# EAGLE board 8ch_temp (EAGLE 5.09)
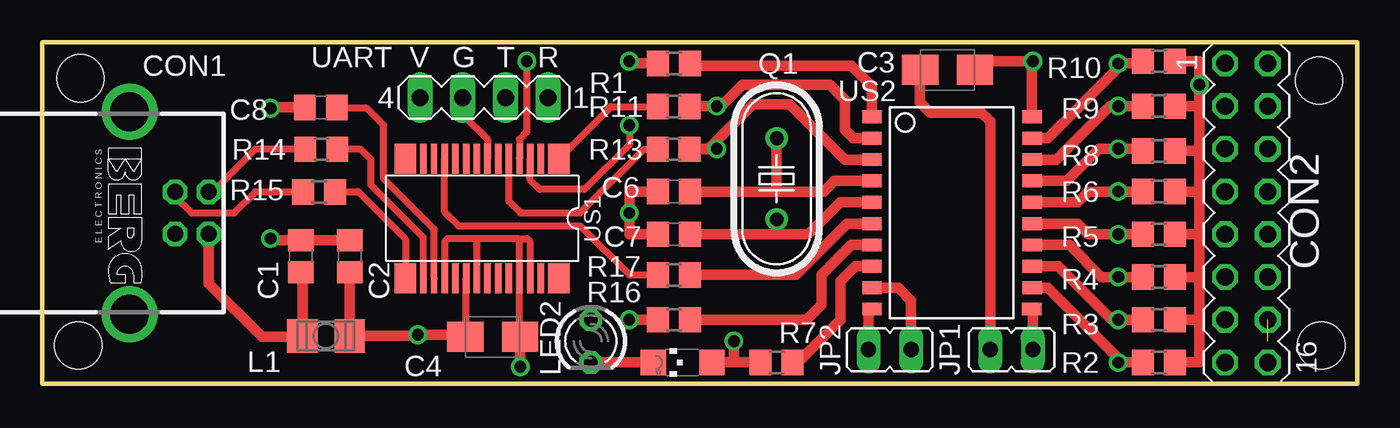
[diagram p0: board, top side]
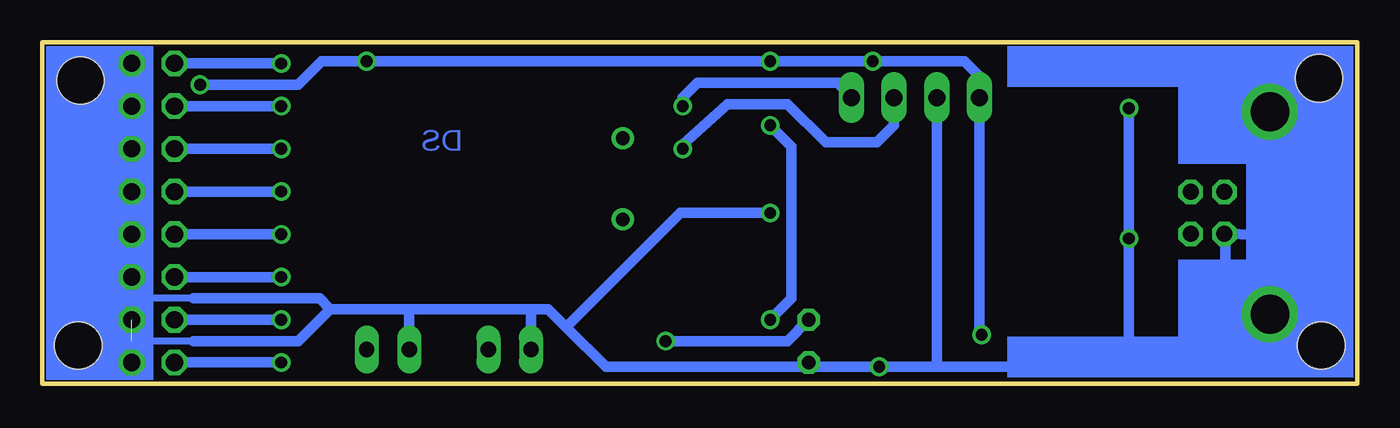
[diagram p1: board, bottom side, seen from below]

Size 78.23 x 20.32 mm. Coordinates in mm from the lower left corner, seen from the top.
Outline: 0,0 0,20.32 78.23,20.32 78.23,0 0,0
Copper layers (1*16): Top 0.035mm / dielectric 1.5mm / Bottom 0.035mm
Design rules "default": minimum track width 10mil, minimum drill 24mil, track to track 8mil, track to pad 8mil, pad to pad 8mil, via to via 8mil, smd to smd 8mil, copper to edge 40mil, drill to drill 8mil, minimum pad ring 10mil, minimum via ring 8mil, stop-mask expansion 4mil, vias tented up to drill 0mil, thermal gap 10mil
Holes 2.8 mm at 2.29,18.16 75.95,18.03 76.07,2.29 2.16,2.29

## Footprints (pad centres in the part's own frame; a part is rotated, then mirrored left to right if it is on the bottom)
C0805 = smd 1.3 x 1.5: 1 -0.95,0; 2 0.95,0
B/3528-21W = smd 2.15 x 1.8: + 1.625,0; - -1.625,0
PN61729-S = drill 0.95 octagon: 1 1.25,4.71; 2 -1.25,4.71; 3 -1.25,2.71; 4 1.25,2.71 | drill 2.3 pad 2.9 round: S1 -6.02,0; S2 6.02,0
MA08-2 = drill 1.016 octagon: 1 -8.89,-1.27; 2 -8.89,1.27; 3 -6.35,-1.27; 4 -6.35,1.27; 5 -3.81,-1.27; 6 -3.81,1.27; 7 -1.27,-1.27; 8 -1.27,1.27; 9 1.27,-1.27; 10 1.27,1.27; 11 3.81,-1.27; 12 3.81,1.27; 13 6.35,-1.27; 14 6.35,1.27; 15 8.89,-1.27; 16 8.89,1.27
JP1 = drill 0.914 long: 1 0,-1.27; 2 0,1.27
L3225P = smd 1.8 x 2: 1 -1.4,0; 2 1.4,0
LED3MM = drill 0.813 octagon: A -1.27,0; K 1.27,0
CHIPLED_1206 = smd 1.5 x 1.5: A 0,-1.75; C 0,1.75
HC49U70 = drill 0.813 round: 1 -2.413,0; 2 2.413,0
R0805 = smd 1.3 x 1.5: 1 -0.95,0; 2 0.95,0
MA04-1 = drill 1.016 long: 1 -3.81,0; 2 -1.27,0; 3 1.27,0; 4 3.81,0
TSSOP28 = smd 1.27 x 1.778: 1 -4.547,-3.556; 14 4.572,-3.556; 15 4.572,3.556; 28 -4.547,3.556 | smd 0.381 x 1.778: 2 -3.48,-3.556; 3 -2.845,-3.556; 4 -2.21,-3.556; 5 -1.575,-3.556; 6 -0.94,-3.556; 7 -0.305,-3.556; 8 0.33,-3.556; 9 0.965,-3.556; 10 1.6,-3.556; 11 2.235,-3.556; 12 2.87,-3.556; 13 3.505,-3.556; 16 3.505,3.556; 17 2.87,3.556; 18 2.235,3.556; 19 1.6,3.556; 20 0.965,3.556; 21 0.33,3.556; 22 -0.305,3.556; 23 -0.94,3.556; 24 -1.575,3.556; 25 -2.21,3.556; 26 -2.845,3.556; 27 -3.48,3.556
SO20L = smd 0.762 x 1.143: 1 -5.08,-5.131; 2 -3.81,-5.131; 3 -2.54,-5.131; 4 -1.27,-5.131; 5 0,-5.131; 6 1.27,-5.131; 7 2.54,-5.131; 8 3.81,-5.131; 9 5.08,-5.131; 10 6.35,-5.131; 11 6.35,4.369; 12 5.08,4.394; 13 3.81,4.394; 14 2.54,4.394; 15 1.27,4.394; 16 0,4.394; 17 -1.27,4.394; 18 -2.54,4.394; 19 -3.81,4.394; 20 -5.08,4.394

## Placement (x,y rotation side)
C1  100nF  [C0805]  15.39,7.59 90 top
C2  100nF  [C0805]  18.31,7.59 90 top
C3  [B/3528-21W]  53.85,18.67 0 top
C4  [B/3528-21W]  26.8,2.79 180 top
C6  100nF  [C0805]  37.59,11.43 0 top
C7  100nF  [C0805]  37.59,8.89 0 top
C8  10nF  [C0805]  16.59,16.43 180 top
CON1  USB  [PN61729-S]  5.21,10.16 270 top
CON2  [MA08-2]  71.63,10.16 270 top
JP1  [JP1]  57.66,2.03 270 top
JP2  [JP1]  50.42,2.03 270 top
L1  10uH  [L3225P]  16.89,2.84 0 top
LED1  [LED3MM]  32.64,2.54 270 top
LED2  [CHIPLED_1206]  38.1,1.27 90 top
Q1  [HC49U70]  43.69,12.19 90 top
R1  1k  [R0805]  37.59,19.05 0 top
R2  1k  [R0805]  66.42,1.27 180 top
R3  1k  [R0805]  66.42,3.81 180 top
R4  1k  [R0805]  66.42,6.35 180 top
R5  1k  [R0805]  66.42,8.89 180 top
R6  1k  [R0805]  66.42,11.43 180 top
R7  1k  [R0805]  43.69,1.27 0 top
R8  1k  [R0805]  66.42,13.84 180 top
R9  1k  [R0805]  66.42,16.51 180 top
R10  1k  [R0805]  66.42,19.18 180 top
R11  47R  [R0805]  37.57,16.48 0 top
R13  47R  [R0805]  37.57,13.94 0 top
R14  47R  [R0805]  16.61,13.94 0 top
R15  47R  [R0805]  16.48,11.4 0 top
R16  47R  [R0805]  37.59,3.81 0 top
R17  47R  [R0805]  37.59,6.48 0 top
UART  [MA04-1]  26.29,17.02 180 top
US1  [TSSOP28]  26.19,9.83 180 top
US2  AT90S2313S  [SO20L]  54.48,10.79 270 top

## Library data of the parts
C1-C4 C6-C8 L1 R1-R11 R13-R17 = rcl
CON1 = con-berg
CON2 UART = con-lstb
JP1 JP2 = jumper
LED1 LED2 = led
Q1 = crystal
US1 = DS
US2 = avr-4

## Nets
+5V: C2.1 C3.+ C4.+ L1.2 R1.1 R2.1 R3.1 R4.1 R5.1 R6.1 R8.1 R9.1 R10.1 UART.4 US1.4 US1.20 US2.20
CF1: JP1.2 US2.11
CF2: JP2.2 US2.9
CL6: C7.2 Q1.1 US2.5
CTS: R17.2 US2.6
GND: C1.2 C2.2 C3.- C4.- C6.1 C7.1 C8.2 CON1.4 CON1.S1 CON1.S2 CON2.2 CON2.4 CON2.6 CON2.8 CON2.10 CON2.12 CON2.14 CON2.16 JP1.1 JP2.1 LED1.K LED2.C UART.3 US1.7 US1.18 US1.21 US1.25 US1.26 US2.10
IO1: CON2.1 R10.2 US2.19
IO2: CON2.3 R9.2 US2.18
IO3: CON2.5 R8.2 US2.17
IO4: CON2.7 R6.2 US2.16
IO5: CON2.9 R5.2 US2.15
IO6: CON2.11 R4.2 US2.14
IO7: CON2.13 R3.2 US2.13
IO8: CON2.15 R2.2 US2.12
N$1: R14.2 US1.16
N$2: R15.2 US1.15
N$3: CON1.2 R14.1
N$4: CON1.3 R15.1
N$6: C8.1 US1.17
N$7: R16.1 US1.3
N$10: R11.1 US1.1
N$11: R13.1 US1.5
N$18: R17.1 US1.11
N$29: C6.2 Q1.2 US2.4
N$31: R1.2 US2.1
N$32: LED1.A LED2.A R7.1
P_ON: R7.2 US2.8
RTS: R16.2 US2.7
RXD: R11.2 UART.1 US2.2
TXD: R13.2 UART.2 US2.3
USB+: C1.1 CON1.1 L1.1

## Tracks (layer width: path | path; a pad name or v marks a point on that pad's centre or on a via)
+5V  (via drill 0.7)
  Top 0.406: 58.88,19.13 58.88,19.36 | US1.4 28.4,14.55 28.83,14.99 v28.83,19.18 | US1.20 25.22,2.84 C4.+
  Top 0.61: R10.1 68.83,19.18 v68.83,17.78 68.83,16.51 | 68.83,3.81 68.83,1.27 R2.1 | 68.83,8.89 68.83,6.35 | 68.83,13.84 68.83,11.43 | 68.83,16.51 R9.1 | 68.83,13.84 R8.1 | 68.83,16.51 68.83,13.84 | 68.83,11.43 R6.1 | 68.83,8.89 R5.1 | 68.83,11.43 68.83,8.89 | 68.83,6.35 R4.1 | 68.83,3.81 R3.1 | 68.83,6.35 68.83,3.81 | US2.20 58.88,19.13 v58.93,19.18 55.88,19.18 C3.+ | R1.1 34.8,19.05 v34.92,19.18 | C4.+ 24.64,2.79 24.51,2.92 v22.35,2.92 22.28,2.85 L1.2 18.29,6.11 C2.1
  Bottom 0.61: v68.83,17.78 62.99,17.78 61.59,19.18 v58.93,19.18 v34.92,19.18 v28.83,19.18 23.37,19.18 22.48,18.29 UART.4 22.48,3.18 22.35,3.05 v22.35,2.92
CF1
  Top 0.61: US2.11 58.93,4.45 JP1.2
CF2
  Top 0.61: US2.9 50.93,5.71 51.69,4.95 JP2.2
CL6
  Top 0.61: C7.2 43.69,8.89 | 43.69,8.89 45.59,8.89 47.5,10.79 US2.5 | 43.69,8.89 Q1.1
CTS
  Top 0.61: US2.6 47.88,9.52 44.83,6.48 R17.2
GND  (via drill 0.7)  (1 unrouted)
  Top 0.406: US1.7 26.49,14.53 25.02,16 UART.3 | US1.26 29.03,8.43 28.83,8.64 28.32,8.64 | US1.18 23.95,8.46 24.13,8.64 25.91,8.64 | 28.32,8.64 25.91,8.64 | 28.32,8.64 28.4,8.56 US1.25 28.4,2.56 C4.- | US1.21 25.86,8.59 25.91,8.64
  Top 0.61: US2.10 49.15,4.45 JP2.1 | C3.- 52.22,16.74 52.83,16.13 55.88,16.13 56.39,15.62 JP1.1 | LED1.K LED2.C | C6.1 34.92,11.43 v34.92,10.16 34.92,8.89 C7.1 | C4.- 28.42,1.04 v28.45,1.02 | C2.2 C1.2 13.68,8.54 v13.59,8.64 | C8.2 13.64,16.43 v13.59,16.38
  Bottom 0.406: 69.22,2.54 72.9,2.54 | 69.22,5.08 72.9,5.08
  Bottom 0.61: CON2.2 CON2.4 CON2.6 CON2.8 CON2.10 CON2.12 72.9,5.08 CON2.14 72.9,2.54 CON2.16 | 61.09,4.45 62.99,2.54 69.22,2.54 | 49.15,4.45 56.39,4.45 | 56.39,4.45 61.09,4.45 | 47.05,3.37 44.7,1.02 32.64,1.02 | 47.05,3.37 48.13,4.45 49.15,4.45 | 24.89,1.02 v28.45,1.02 32.64,1.02 | 56.39,4.45 JP1.1 | 49.15,4.45 JP2.1 | 32.64,1.02 LED1.K | v34.92,10.16 40.26,10.16 47.05,3.37 | UART.3 25.02,1.14 24.89,1.02 | 13.59,1.02 24.89,1.02 | 13.59,1.02 v13.59,8.64 v13.59,16.38 | 13.59,1.02 10.41,1.02 7.87,3.56 7.87,3.81 | 7.87,3.81 7.87,8.87 CON1.4 5.08,8.83 CON1.S1 | CON1.S2 7.54,4.14 7.87,3.81 | 61.09,4.45 61.72,5.08 69.22,5.08
IO1  (via drill 0.7)
  Top 0.61: R10.2 65.47,19.05 v64.01,19.05 64.01,18.8 59.82,14.61 US2.19
  Bottom 0.61: v64.01,19.05 CON2.1
IO2  (via drill 0.7)
  Top 0.61: R9.2 v64.01,16.51 63.5,16.51 60.33,13.34 US2.18
  Bottom 0.61: v64.01,16.51 CON2.3
IO3  (via drill 0.7)
  Top 0.61: R8.2 65.47,13.97 v64.01,13.97 62.87,13.97 60.96,12.07 US2.17
  Bottom 0.61: v64.01,13.97 CON2.5
IO4  (via drill 0.7)
  Top 0.61: R6.2 v64.01,11.43 62.23,11.43 61.59,10.79 US2.16
  Bottom 0.61: v64.01,11.43 CON2.7
IO5  (via drill 0.7)
  Top 0.61: R5.2 v64.01,8.89 62.23,8.89 61.59,9.52 US2.15
  Bottom 0.61: v64.01,8.89 CON2.9
IO6  (via drill 0.7)
  Top 0.61: R4.2 v64.01,6.35 62.99,6.35 61.09,8.25 US2.14
  Bottom 0.61: v64.01,6.35 CON2.11
IO7  (via drill 0.7)
  Top 0.61: R3.2 v64.01,3.81 63.63,3.81 60.45,6.98 US2.13
  Bottom 0.61: v64.01,3.81 CON2.13
IO8  (via drill 0.7)
  Top 0.61: R2.2 v64.01,1.27 64.01,1.52 59.82,5.71 US2.12
  Bottom 0.61: v64.01,1.27 CON2.15
N$1
  Top 0.406: R14.2 18.95,13.95 19.56,13.34 19.56,11.81 22.68,8.69 US1.16
N$2
  Top 0.406: US1.15 21.61,8.61 18.8,11.43 17.46,11.43 R15.2
N$3
  Top 0.406: CON1.2 10.14,11.41 12.7,13.97 15.64,13.97 R14.1
N$4
  Top 0.406: CON1.3 7.92,11.13 8.89,10.16 11.43,10.16 12.7,11.43 15.51,11.43 R15.1
N$6
  Top 0.406: US1.17 23.32,9.2 20.32,12.19 20.32,15.37 19.3,16.38 17.71,16.38 C8.1
N$7  (via drill 0.7)
  Top 0.406: v34.92,15.37 34.92,14.22 32.26,11.56 29.59,11.56 29.03,12.12 US1.3
  Top 0.61: v34.92,3.81 R16.1
  Bottom 0.61: v34.92,3.81 33.66,5.08 33.66,14.1 v34.92,15.37
N$10
  Top 0.406: R11.1 33.83,16.48 US1.1
N$11
  Top 0.406: R13.1 35.79,13.95 32,10.16 28.45,10.16 27.76,10.85 US1.5
N$18
  Top 0.406: R17.1 34.92,6.48 32,9.4 24.77,9.4 23.95,10.21 US1.11
N$29
  Top 0.61: C6.2 43.81,11.43 | 43.81,11.43 46.48,11.43 47.12,12.07 US2.4 | Q1.2 43.69,11.56 43.81,11.43
N$31
  Top 0.61: US2.1 49.35,17.7 48.13,18.92 38.67,18.92 R1.2
N$32  (via drill 0.7)
  Top 0.61: 41.15,1.27 R7.1 | 41.15,1.27 LED2.A | v41.15,2.54 41.15,1.27
  Bottom 0.61: v41.15,2.54 33.91,2.54 LED1.A
P_ON
  Top 0.61: US2.8 48.39,6.98 47.5,6.1 47.5,3.81 44.96,1.27 R7.2
RTS
  Top 0.61: US2.7 48.13,8.25 46.36,6.48 46.36,4.7 45.47,3.81 R16.2
RXD  (via drill 0.7)
  Top 0.406: R11.2 40.11,16.48 v40.13,16.51
  Top 0.61: US2.2 48.26,14.61 47.75,15.11 47.75,16.89 46.86,17.78 41.66,17.78 40.39,16.51 v40.13,16.51 38.54,16.51 R11.2
  Bottom 0.61: v40.13,16.51 40.13,17.02 39.24,17.91 30.86,17.91 UART.1
TXD  (via drill 0.7)
  Top 0.61: US2.3 47.75,13.34 44.45,16.64 42.29,16.64 39.62,13.97 38.54,13.97 R13.2 40.11,13.95 v40.13,13.97
  Bottom 0.61: v40.13,13.97 40.13,14.22 37.47,16.64 33.91,16.64 31.62,14.35 28.57,14.35 27.56,15.37 UART.2
USB+
  Top 0.61: C1.1 15.49,6.11 L1.1 15.44,2.79 13.08,2.79 9.92,5.96 CON1.1
(copper drawn outside any net)
  shapes: Bottom area x6

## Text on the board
Bottom: DS
tPlace: V | G | T | R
